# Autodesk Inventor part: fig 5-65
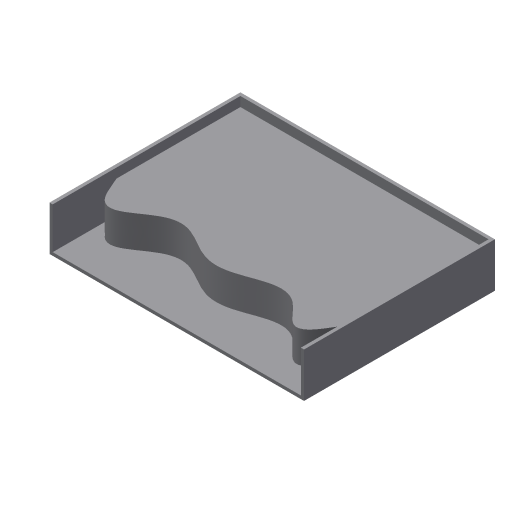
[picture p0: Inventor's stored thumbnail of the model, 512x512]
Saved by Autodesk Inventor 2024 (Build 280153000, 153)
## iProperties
Created: 2004-05
Part Number: fig 5-65
Document SubType Name: Modeling
Designer: CADCIM Technologies
Manufacturer: Standard
Standards Organization: Custom
Density: 1 g/cm^3
Material: Generic
Appearance: Default
Author: CADCIM Technologies
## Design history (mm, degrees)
sketch "Sketch1"
  geometry: L1 (-40, -30)-(40, -30); L2 (40, -30)-(40, 30); L3 (40, 30)-(-40, 30); L4 (-40, 30)-(-40, -30); 1 further point
  constraints: 8 end point, 2 parallel, 1 horizontal, 1 perpendicular, 1 other
  dimensions: "d0" = 80 distance of L1.start L1.end; "d1" = 60 distance of L3.end L1.start; "d2" = 30 distance from line of point (0, 0) L1; "d3" = 40 distance from line of point (0, 0) L4
extrude "Extrusion1" new body sketch "Sketch1" distance "d4" = 14; taper "d5" = 0 deg
shell "Shell1" dims "d6" = 1
workplane "Work Plane1"
sketch "Sketch2"
  geometry: L1 (78, -13)-(78, -11.813); L2 (0, -11.813)-(0, -13); L3 (0, -13)-(78, -13); L4 (0, -11.813)-(17.826, -3.295); L5 (17.826, -3.295)-(60.174, -3.295); L6 (60.174, -3.295)-(78, -11.813); L7 (79, -13.795)-(78, -13.795); L8 (78, 0)-(78, -13) reference; L9 (0, -13)-(0, 0) reference; L10 (78, -13)-(0, -13) reference
  constraints: 14 end point, 3 collinear, 2 equal length, 2 vertical, 1 horizontal alignment, 1 parallel, 1 point on line
extrude "Extrusion2" join sketch "Sketch2" stored distance "d8" = 14; taper "d9" = 0 deg
workplane "Work Plane2"
sketch "Sketch4"
  geometry: 7 further points
  constraints: 7 other
extrude "Extrusion9" join sketch "Sketch4" distance "d35" = 10; taper "d36" = 0 deg
body "Solid1"
other parameters: "d7" = 23, "d18" = 4
